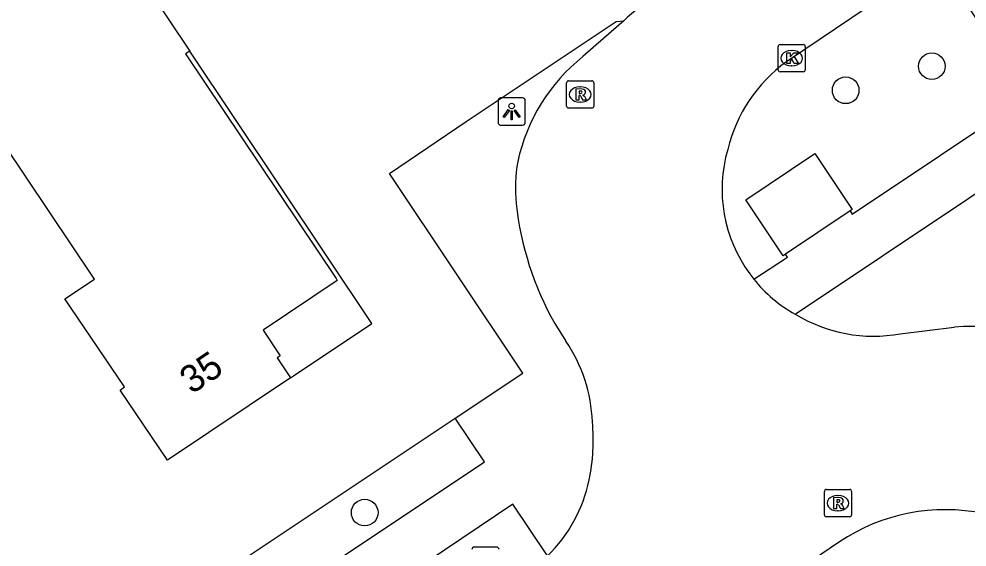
# Model space of a CAD drawing. Extents: x 158797 to 159887, y 384318 to 385255.
# Drawn here: x 159001.4 to 159036.2, y 384811.56 to 384830.95 of the extents above; entities that cross this region are included whole.
import ezdxf

# ---------------------------------------------------------------- set-up
doc = ezdxf.new("R2010")
doc.units = 0
for name, color, linetype in [('IMGEO_Boom', 7, 'Continuous'), ('IMGEO_Groenvoorziening', 7, 'Continuous'), ('IMGEO_Kolk', 7, 'Continuous'), ('IMGEO_Lage_trafo', 7, 'Continuous'), ('IMGEO_Lichtpunt', 7, 'Continuous'), ('IMGEO_Pand', 7, 'Continuous'), ('IMGEO_Pand_nummerreeks', 7, 'Continuous'), ('IMGEO_Pand_overbouw', 7, 'Continuous'), ('IMGEO_Rijbaan_lokaal_open', 7, 'Continuous'), ('IMGEO_Rioolput', 7, 'Continuous'), ('IMGEO_Voetpad_open', 7, 'Continuous')]:
    doc.layers.add(name, color=color, linetype=linetype)

msp = doc.modelspace()

# ---------------------------------------------------------------- linework, layer by layer
at = {"layer": 'IMGEO_Boom'}
for centre in [(159034.907, 384829.211), (159031.745, 384828.327), (159014.089, 384812.823)]:
    msp.add_circle(centre, 0.489, dxfattribs=at)
at = {"layer": 'IMGEO_Groenvoorziening'}
msp.add_lwpolyline([(159009.377, 384810.926), (159017.413, 384816.287)], dxfattribs=at)
at = {"layer": 'IMGEO_Kolk'}
for p, q in [((159029.263, 384829.079), (159029.263, 384829.931)), ((159029.338, 384830.005), (159030.19, 384830.005)), ((159030.264, 384829.931), (159030.264, 384829.079)), ((159029.751, 384829.785), (159029.776, 384829.785)), ((159029.774, 384829.225), (159029.749, 384829.225)), ((159030.19, 384829.005), (159029.338, 384829.005))]:
    msp.add_line(p, q, dxfattribs=at)
for points in [[(159029.263, 384829.079), (159029.263, 384829.931)], [(159029.338, 384830.005), (159030.19, 384830.005)], [(159030.264, 384829.931), (159030.264, 384829.079)], [(159029.584, 384829.705), (159029.707, 384829.705), (159029.707, 384829.554), (159029.837, 384829.705), (159030.001, 384829.705), (159029.855, 384829.554), (159030.008, 384829.305), (159029.856, 384829.305), (159029.771, 384829.469), (159029.707, 384829.402), (159029.707, 384829.305), (159029.584, 384829.305), (159029.584, 384829.705)], [(159030.19, 384829.005), (159029.338, 384829.005)]]:
    msp.add_lwpolyline(points, dxfattribs=at)
for centre, start, end in [((159029.34, 384829.929), 91.552, 178.448), ((159029.34, 384829.929), 91.552, 178.448), ((159030.188, 384829.929), 1.552, 88.448), ((159030.188, 384829.929), 1.552, 88.448), ((159029.34, 384829.081), 181.552, 268.448), ((159029.34, 384829.081), 181.552, 268.448), ((159030.188, 384829.081), 271.552, 358.448), ((159030.188, 384829.081), 271.552, 358.448)]:
    msp.add_arc(centre, 0.0765, start, end, dxfattribs=at)
for centre, major_axis, ratio, start_param, end_param in [((159029.75, 384829.505), (-0.387, 0.002), 0.722429, 4.712389, 7.853982), ((159029.775, 384829.505), (-0.39, 0.002), 0.717154, 1.570796, 4.712389)]:
    msp.add_ellipse(centre, major_axis=major_axis, ratio=ratio, start_param=start_param, end_param=end_param, dxfattribs=at)
at = {"layer": 'IMGEO_Lage_trafo'}
for points in [[(159029.538, 384822.316), (159029.446, 384822.255), (159028.086, 384824.303), (159030.609, 384826.011), (159031.985, 384823.948), (159031.911, 384823.899)], [(159031.911, 384823.899), (159029.538, 384822.316)]]:
    msp.add_lwpolyline(points, dxfattribs=at)
at = {"layer": 'IMGEO_Lichtpunt'}
for p, q in [((159018.986, 384827.952), (159018.986, 384827.145)), ((159018.986, 384827.952), (159018.986, 384827.145)), ((159019.888, 384828.047), (159019.08, 384828.047)), ((159019.888, 384828.047), (159019.08, 384828.047)), ((159019.982, 384827.145), (159019.982, 384827.952)), ((159019.982, 384827.145), (159019.982, 384827.952)), ((159019.08, 384827.051), (159019.888, 384827.051)), ((159019.08, 384827.051), (159019.888, 384827.051)), ((159018.927, 384811.559), (159018.119, 384811.559)), ((159018.927, 384811.559), (159018.119, 384811.559))]:
    msp.add_line(p, q, dxfattribs=at)
for points in [[(159019.36, 384827.616), (159019.399, 384827.588), (159019.211, 384827.326), (159019.173, 384827.353), (159019.36, 384827.616)], [(159019.462, 384827.568), (159019.509, 384827.568), (159019.509, 384827.246), (159019.462, 384827.246), (159019.462, 384827.568)], [(159019.572, 384827.588), (159019.61, 384827.615), (159019.797, 384827.353), (159019.758, 384827.325), (159019.572, 384827.588)]]:
    msp.add_lwpolyline(points, dxfattribs=at)
msp.add_circle((159019.485, 384827.75), 0.0994, dxfattribs=at)
for centre, start, end in [((159019.08, 384827.952), 90, 180), ((159019.08, 384827.952), 90, 180), ((159019.888, 384827.952), 0, 90), ((159019.888, 384827.952), 0, 90), ((159019.08, 384827.145), 180, 270), ((159019.08, 384827.145), 180, 270), ((159019.888, 384827.145), 270, 0), ((159019.888, 384827.145), 270, 360), ((159018.119, 384811.464), 90, 180), ((159018.119, 384811.464), 90, 180), ((159018.927, 384811.464), 0, 90), ((159018.927, 384811.464), 0, 90)]:
    msp.add_arc(centre, 0.0946, start, end, dxfattribs=at)
at = {"layer": 'IMGEO_Pand'}
msp.add_lwpolyline([(158998.352, 384830.067), (159001.8, 384832.363), (158998.598, 384837.128), (159001.316, 384838.955), (159005.13, 384833.279), (159005.266, 384833.371), (159007.67, 384829.769), (159007.516, 384829.666), (159013.04, 384821.413), (159013.085, 384821.346), (159010.36, 384819.522), (159010.989, 384818.583), (159010.876, 384818.508), (159011.37, 384817.771), (159006.845, 384814.748), (159005.112, 384817.324), (159005.278, 384817.436), (159003.088, 384820.674), (159004.176, 384821.398), (158998.352, 384830.067)], dxfattribs=at)
at = {"layer": 'IMGEO_Pand_overbouw'}
msp.add_lwpolyline([(159014.348, 384819.761), (159007.67, 384829.769), (159007.516, 384829.666), (159013.04, 384821.413), (159013.085, 384821.346), (159010.36, 384819.522), (159010.989, 384818.583), (159010.876, 384818.508), (159011.37, 384817.771), (159011.478, 384817.844)], close=True, dxfattribs=at)
at = {"layer": 'IMGEO_Rijbaan_lokaal_open'}
for points in [[(159062.256, 384851.349), (159060.561, 384850.194), (159051.296, 384843.964), (159040.9, 384837.091), (159035.001, 384833.037), (159029.568, 384829.373)], [(159023.6, 384830.878), (159022.85, 384830.226), (159022.095, 384829.565)], [(159021.064, 384819.768), (159021.475, 384819.121)], [(159033.749, 384819.386), (159034.735, 384819.508), (159035.734, 384819.63)], [(159031.519, 384811.747), (159027.247, 384808.855), (159019.758, 384803.849)]]:
    msp.add_lwpolyline(points, dxfattribs=at)
for centre, radius, start, end in [((159028.234, 384826.022), 6.712, 120.518, 133.6546), ((159026.359, 384824.263), 6.804, 128.8066, 167.745), ((159032.888, 384824.826), 5.63, 126.1416, 166.3716), ((159032.428, 384824.687), 5.221, 163.6966, 216.3509), ((159025.22, 384824.731), 5.596, 169.9512, 185.7182), ((159031.027, 384825.39), 11.44, 186.1089, 209.437), ((159032.163, 384824.392), 4.833, 215.3947, 218.4345), ((159032.269, 384824.469), 4.963, 218.3633, 241.4419), ((159032.773, 384824.814), 5.515, 238.5542, 280.1904), ((159036.548, 384808.371), 11.289, 66.5884, 94.1329), ((159016.714, 384815.911), 5.742, 2.4483, 33.992), ((159015.18, 384815.505), 7.3, 348.2829, 5.1196), ((159017.014, 384815.12), 5.426, 314.2134, 348.3243), ((159035.395, 384805.995), 6.936, 78.1504, 123.9701)]:
    msp.add_arc(centre, radius, start, end, dxfattribs=at)
at = {"layer": 'IMGEO_Rioolput'}
for p, q in [((159021.5, 384827.749), (159021.5, 384828.601)), ((159021.575, 384828.675), (159022.427, 384828.675)), ((159021.988, 384828.455), (159022.013, 384828.455)), ((159022.501, 384828.601), (159022.501, 384827.749)), ((159022.011, 384827.895), (159021.986, 384827.895)), ((159022.427, 384827.675), (159021.575, 384827.675)), ((159030.963, 384812.746), (159030.963, 384813.598)), ((159031.038, 384813.672), (159031.89, 384813.672)), ((159031.964, 384813.598), (159031.964, 384812.746)), ((159031.451, 384813.452), (159031.476, 384813.452)), ((159031.474, 384812.892), (159031.449, 384812.892)), ((159031.89, 384812.672), (159031.038, 384812.672))]:
    msp.add_line(p, q, dxfattribs=at)
for points in [[(159021.5, 384827.749), (159021.5, 384828.601)], [(159021.575, 384828.675), (159022.427, 384828.675)], [(159022.501, 384828.601), (159022.501, 384827.749)], [(159022.089, 384828.373), (159021.837, 384828.375), (159021.837, 384827.975)], [(159021.837, 384827.975), (159021.961, 384827.975), (159021.961, 384828.137), (159021.972, 384828.137)], [(159022.015, 384828.294), (159021.961, 384828.294), (159021.961, 384828.213)], [(159021.961, 384828.213), (159022.013, 384828.213)], [(159022.019, 384828.108), (159022.09, 384827.975), (159022.23, 384827.975), (159022.165, 384828.101)], [(159022.427, 384827.675), (159021.575, 384827.675)], [(159030.963, 384812.746), (159030.963, 384813.598)], [(159031.038, 384813.672), (159031.89, 384813.672)], [(159031.964, 384813.598), (159031.964, 384812.746)], [(159031.552, 384813.37), (159031.3, 384813.372), (159031.3, 384812.972)], [(159031.3, 384812.972), (159031.424, 384812.972), (159031.424, 384813.134), (159031.435, 384813.134)], [(159031.478, 384813.291), (159031.424, 384813.291), (159031.424, 384813.21)], [(159031.424, 384813.21), (159031.476, 384813.21)], [(159031.482, 384813.105), (159031.553, 384812.972), (159031.693, 384812.972), (159031.628, 384813.098)], [(159031.89, 384812.672), (159031.038, 384812.672)]]:
    msp.add_lwpolyline(points, dxfattribs=at)
for centre, radius, start, end in [((159021.577, 384828.599), 0.0765, 91.552, 178.448), ((159021.577, 384828.599), 0.0765, 91.552, 178.448), ((159022.425, 384828.599), 0.0765, 1.552, 88.448), ((159022.425, 384828.599), 0.0765, 1.552, 88.448), ((159021.971, 384828.084), 0.0533, 26.0293, 88.6989), ((159021.997, 384828.402), 0.19, 274.7715, 282.9687), ((159022.021, 384828.198), 0.0964, 77.0061, 93.1865), ((159022.035, 384828.255), 0.0378, 276.6634, 79.6772), ((159022.088, 384828.263), 0.109, 350.3612, 89.416), ((159022.086, 384828.263), 0.112, 277.5842, 350.9817), ((159022.07, 384828.048), 0.108, 29.5134, 73.7905), ((159021.577, 384827.751), 0.0765, 181.552, 268.448), ((159021.577, 384827.751), 0.0765, 181.552, 268.448), ((159022.425, 384827.751), 0.0765, 271.552, 358.448), ((159022.425, 384827.751), 0.0765, 271.552, 358.448), ((159031.04, 384813.596), 0.0765, 91.552, 178.448), ((159031.04, 384813.596), 0.0765, 91.552, 178.448), ((159031.888, 384813.596), 0.0765, 1.552, 88.448), ((159031.888, 384813.596), 0.0765, 1.552, 88.448), ((159031.434, 384813.081), 0.0533, 26.0293, 88.6989), ((159031.46, 384813.399), 0.19, 274.7715, 282.9687), ((159031.484, 384813.195), 0.0964, 77.0061, 93.1865), ((159031.498, 384813.252), 0.0378, 276.6634, 79.6772), ((159031.551, 384813.26), 0.109, 350.3612, 89.416), ((159031.549, 384813.26), 0.112, 277.5842, 350.9817), ((159031.533, 384813.045), 0.108, 29.5134, 73.7905), ((159031.04, 384812.748), 0.0765, 181.552, 268.448), ((159031.04, 384812.748), 0.0765, 181.552, 268.448), ((159031.888, 384812.748), 0.0765, 271.552, 358.448), ((159031.888, 384812.748), 0.0765, 271.552, 358.448)]:
    msp.add_arc(centre, radius, start, end, dxfattribs=at)
for centre, major_axis, ratio, start_param, end_param in [((159021.987, 384828.175), (-0.387, 0.002), 0.722429, 4.712389, 7.853982), ((159022.012, 384828.175), (-0.39, 0.002), 0.717154, 1.570796, 4.712389), ((159031.45, 384813.172), (-0.387, 0.002), 0.722429, 4.712389, 7.853982), ((159031.475, 384813.172), (-0.39, 0.002), 0.717154, 1.570796, 4.712389)]:
    msp.add_ellipse(centre, major_axis=major_axis, ratio=ratio, start_param=start_param, end_param=end_param, dxfattribs=at)
at = {"layer": 'IMGEO_Voetpad_open'}
for points in [[(159031.911, 384823.899), (159031.99, 384823.78), (159038.428, 384828.093), (159035.883, 384831.966), (159053.058, 384843.462), (159063.047, 384850.2), (159062.256, 384851.349)], [(159017.413, 384816.287), (159019.896, 384817.939), (159015.006, 384825.273), (159017.809, 384827.176), (159023.315, 384830.851), (159023.6, 384830.878)], [(159029.896, 384820.109), (159039.478, 384826.514), (159048.678, 384812.813), (159063.266, 384791.093), (159067.255, 384785.128), (159065.853, 384784.168)], [(159028.377, 384821.388), (159029.614, 384822.202), (159029.538, 384822.316)], [(159009.377, 384810.926), (159009.166, 384809.736), (159009.733, 384808.852), (159018.485, 384814.69), (159017.413, 384816.287)], [(159020.798, 384811.231), (159019.531, 384813.127), (159010.806, 384807.256), (159012.089, 384805.353)]]:
    msp.add_lwpolyline(points, dxfattribs=at)

# ---------------------------------------------------------------- texts
at = {"layer": 'IMGEO_Pand_nummerreeks'}
msp.add_text('35', height=1, rotation=33.7472, dxfattribs=at).set_placement((159007.737, 384817.148))

doc.saveas('drawing.dxf')
